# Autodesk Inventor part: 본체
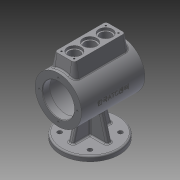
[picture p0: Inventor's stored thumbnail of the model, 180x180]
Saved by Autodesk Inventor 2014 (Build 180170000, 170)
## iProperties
Created: 2015-11
Part Number: 본체
Material: 알루미늄 6061
Document SubType Name: Modeling
Designer: mduedu
Density: 2.71 g/cm^3
Appearance: 기본값
Mass: 1433.81 g
Surface Area: 1290.12 cm^2
Volume: 529.082 cm^3
Author: mduedu
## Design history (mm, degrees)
sketch "스케치2"
  geometry: C1 r 47.5 at (0, 0); 1 further point
  constraints: 1 centre point, 1 coincident
  dimensions: "d147" = 95 diameter of C1
extrude "돌출1" new body sketch "스케치2" stored distance "d12" = 130; taper "d13" = 0 deg
feature "쉘1" dims "d31" = 15, "d32" = 6, "d33" = 15
sketch "스케치5"
  geometry: C1 r 32.5 at (0, 0); 1 further point
  constraints: 1 centre point, 1 coincident
  dimensions: "d34" = 65 diameter of C1
extrude "돌출3" cut sketch "스케치5" stored distance "d36" = 3; taper "d37" = 0 deg
node "작업 평면1"
sketch "스케치6"
  geometry: L1 (-60, -55)-(60, -55); L2 (60, -55)-(60, 55); L3 (60, 55)-(-60, 55); L4 (-60, 55)-(-60, -55); L5 (-60, -55)-(60, 55); L6 (60, -55)-(-60, 55); C1 r 60 at (0, 0); 1 further point
  constraints: 12 end point, 2 midpoint, 2 parallel, 1 centre point, 1 coincident, 1 horizontal, 1 perpendicular
  dimensions: "d41" = 110 distance of L3.end L1.start; "d43" = 120 distance of L2.end L3.end; "d199" = 120 diameter of C1
extrude "돌출4" join sketch "스케치6" distance "d44" = 10; taper "d45" = 0 deg
sketch "스케치19"
  geometry: L1 (-5, 40)-(5, 40); L2 (5, 40)-(5, -40); L3 (5, -40)-(-5, -40); L4 (-5, -40)-(-5, 40); L5 (-60, 55)-(-60, -55) reference; L6 (5, -40)-(-5, 40); L7 (5, 40)-(-5, -40); 3 further points
  constraints: 12 end point, 2 midpoint, 2 parallel, 1 coincident, 1 horizontal, 1 horizontal alignment, 1 perpendicular
  dimensions: "d151" = 10 distance of L1.start L1.end; "d152" = 80 distance of L3.end L1.start
extrude "돌출9" join sketch "스케치19" stored distance "d153" = 10; taper "d154" = 0 deg
feature "면 기울기2" dims angle "d198" = 15 deg
sketch "스케치20"
  geometry: L1 (65, 32.5)-(50, 32.5) reference; L2 (50, 32.5)-(50, 41.5) reference; L3 (50, 41.5)-(-50, 41.5) reference; L4 (-50, 41.5)-(-50, 32.5) reference; L5 (-50, 32.5)-(-65, 32.5) reference; L6 (-65, 32.5)-(-65, 47.5) reference; L7 (-65, 47.5)-(65, 47.5) reference; L8 (65, 47.5)-(65, 32.5) reference; L9 (50, -32.5)-(65, -32.5) reference; L10 (65, -32.5)-(65, -47.5) reference; L11 (65, -47.5)-(5, -47.5) reference; L12 (5, -47.5)-(5, -90) reference; L13 (5, -90)-(60, -90) reference; L14 (60, -100)-(-60, -100) reference; L15 (-60, -90)-(-5, -90) reference; L16 (-5, -90)-(-5, -47.5) reference; L17 (-5, -47.5)-(-65, -47.5) reference; L18 (-65, -47.5)-(-65, -32.5) reference; L19 (-65, -32.5)-(-50, -32.5) reference; L20 (-50, -32.5)-(-50, -41.5) reference; L21 (-50, -41.5)-(50, -41.5) reference; L22 (50, -41.5)-(50, -32.5) reference; L23 (-40, -90)-(-28.612, -47.5); L24 (60, -90)-(60, -100) reference; L25 (-60, -100)-(-60, -90) reference; 1 further point
  constraints: 2 end point, 2 point on line
  dimensions: "d156" = 105 deg angle of L23 L15; "d200" = 20 distance from line of L23.start L25
feature "리브2" sketch "스케치20" dims "d157" = 1, "d158" = 10, "d159" = 0, "d160" = 0, "d161" = 1, "d162" = 1
fillet "모깎기21" dims "d163" = 3
fillet "모깎기22" dims "d164" = 3
fillet "모깎기23" dims "d165" = 3
sketch "스케치21" dims "d166" = 78
  geometry: 3 further points
  constraints: 2 horizontal alignment, 1 coincident, 2 other
hole "구멍6" sketch "스케치21" at (39, 0) diameter "d168" = 3.242; stored, may be unused: countersink angle "d172" = 90 deg, drill point angle "d174" = 118 deg; dims "d169" = 9, "d170" = 4, "d171" = 2, "d173" = 11
node "작업 평면2"
sketch "스케치13"
  geometry: L1 (-52.5, -20)-(52.5, -20); L2 (52.5, -20)-(52.5, 20); L3 (52.5, 20)-(-52.5, 20); L4 (-52.5, 20)-(-52.5, -20); L5 (-52.5, -20)-(52.5, 20); L6 (52.5, -20)-(-52.5, 20); 1 further point
  constraints: 12 end point, 2 midpoint, 2 parallel, 1 horizontal, 1 perpendicular
  dimensions: "d93" = 105 distance of L2.end L3.end; "d95" = 40 distance of L1.end L2.end
extrude "돌출8" join sketch "스케치13" stored distance "d96" = 80; taper "d97" = 0 deg
fillet "모깎기15" dims "d98" = 5
feature "면 기울기1" dims angle "d178" = 10 deg
fillet "모깎기24" dims "d179" = 3
sketch "스케치14"
  geometry: L1 (-52.5, 15)-(-52.5, -15) reference; L2 (52.5, -15)-(52.5, 15) reference; L3 (-52.5, 0)-(52.5, 0); 4 further points
  constraints: 2 end point, 2 midpoint, 2 point on line, 1 coincident
  dimensions: "d100" = 32 distance of point (-32, 0) point (0, 0); "d102" = 32 distance of point (32, 0) point (0, 0) (derived)
hole "구멍3" sketch "스케치14" at (-32, 0), (0, 0), (32, 0) diameter "d103" = 22; stored, may be unused: countersink angle "d107" = 90 deg, drill point angle "d109" = 118 deg; dims "d104" = 8, "d105" = 28, "d106" = 5, "d108" = 10
sketch "스케치15"
  geometry: L1 (45.5, -13)-(-45.5, -13); L2 (-45.5, -13)-(-45.5, 13); L3 (-45.5, 13)-(45.5, 13); L4 (45.5, 13)-(45.5, -13); L5 (45.5, -13)-(-45.5, 13); L6 (-45.5, -13)-(45.5, 13); L7 (47.5, 20)-(-47.5, 20) reference; L8 (-52.5, 15)-(-52.5, -15) reference; 5 further points
  constraints: 12 end point, 4 coincident, 2 midpoint, 2 parallel, 1 horizontal, 1 perpendicular
  dimensions: "d110" = 7 distance between parallel lines of L3 L7; "d111" = 7 distance between parallel lines of L2 L8 (derived)
hole "구멍4" sketch "스케치15" at (-45.5, 13), (45.5, 13), (45.5, -13), (-45.5, -13) diameter "d112" = 3.242; stored, may be unused: countersink angle "d116" = 90 deg, drill point angle "d118" = 118 deg; dims "d113" = 10, "d114" = 28, "d115" = 5, "d117" = 13
node "작업 평면3"
chamfer "모따기2" distance "d183" = 1; stored, may be unused: second distance "d184" = 2, angle "d185" = 45 deg
fillet "모깎기26" dims "d194" = 3
sketch "스케치24"
  geometry: L1 (-31.113, -31.113)-(31.113, -31.113); L2 (31.113, -31.113)-(31.113, 31.113); L3 (31.113, 31.113)-(-31.113, 31.113); L4 (-31.113, 31.113)-(-31.113, -31.113); L5 (-31.113, -31.113)-(31.113, 31.113); L6 (31.113, -31.113)-(-31.113, 31.113); 1 further point
  constraints: 12 end point, 2 midpoint, 2 parallel, 2 perpendicular, 1 horizontal
  dimensions: "d201" = 88 distance of L1.start L2.end
hole "구멍8" sketch "스케치24" at (-31.113, -31.113), (31.113, 31.113), (31.113, -31.113), (-31.113, 31.113) diameter "d203" = 9; stored, may be unused: countersink angle "d207" = 90 deg, drill point angle "d209" = 118 deg; dims "d204" = 6, "d205" = 4, "d206" = 2, "d208" = 8
sketch "스케치22"
  geometry: 2 further points
  constraints: 1 coincident, 1 other
feature "엠보싱3" sketch "스케치22" dims "d31" = 15, "d93" = 105, "d95" = 40, "d181" = 0.5, "d182" = 0
node "솔리드1"
mirror "대칭6"
pattern_circular "원형 패턴2" dims angle "d176" = 360 deg
mirror "대칭5"
node "절단 모서리 투영1"
